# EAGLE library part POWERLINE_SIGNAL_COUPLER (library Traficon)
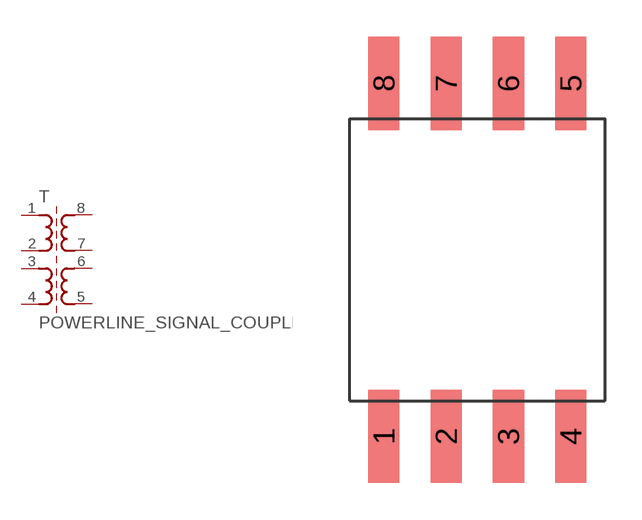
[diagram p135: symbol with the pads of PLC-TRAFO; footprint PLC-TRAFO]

Designator prefix T

## POWERLINE_SIGNAL_COUPLER  [PLC-TRAFO]
1  1  pas
2  2  pas
3  3  pas
4  4  pas
5  5  pas
6  6  pas
7  7  pas
8  8  pas

## Footprint PLC-TRAFO (pad centres in mm)
CT (04/03/2008): changed pin names from P$n to n
smd 1.27 x 3.8: 1 -3.81,-7.2; 2 -1.27,-7.2; 3 1.27,-7.2; 4 3.81,-7.2; 5 3.81,7.2; 6 1.27,7.2; 7 -1.27,7.2; 8 -3.81,7.2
